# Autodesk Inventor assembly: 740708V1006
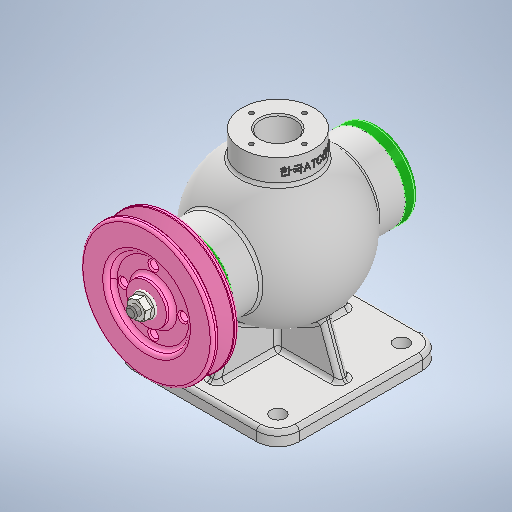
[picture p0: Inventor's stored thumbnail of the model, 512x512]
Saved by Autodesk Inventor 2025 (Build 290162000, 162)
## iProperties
Created: 2024-07
Part Number: 740708V1006
Document SubType Name: Assembly
Designer: parkm
Author: parkm
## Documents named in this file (12)
- C:\Users\parkm\OneDrive\바탕 화면\740708V1006\740708V1006.iam
- C:\Users\parkm\OneDrive\바탕 화면\740708V1006\본체.ipt
- C:\Users\parkm\OneDrive\바탕 화면\740708V1006\뒤커버\뒤커버.ipt
- C:\Users\parkm\OneDrive\바탕 화면\740708V1006\베어링- 6202\베어링- 6202.ipt
- C:\Users\parkm\OneDrive\바탕 화면\740708V1006\편심축\편심축.ipt
- C:\Users\parkm\OneDrive\바탕 화면\740708V1006\칼라\칼라.ipt
- C:\Users\parkm\OneDrive\바탕 화면\740708V1006\앞커버\앞커버.ipt
- C:\Users\parkm\OneDrive\바탕 화면\740708V1006\오일실 15 30 7\오일실 15 30 7.ipt
- C:\Users\parkm\OneDrive\바탕 화면\740708V1006\볼트 M4 x 16\볼트 M4 x 16.ipt
- C:\Users\parkm\OneDrive\바탕 화면\740708V1006\키 4 x 4 x 12\키 4 x 4 x 12.ipt
- C:\Users\parkm\OneDrive\바탕 화면\740708V1006\V-벨트풀리\V-벨트풀리.ipt
- C:\Users\parkm\OneDrive\바탕 화면\740708V1006\너트 M8\너트 M8.ipt
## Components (1 placed, 1 different names)
1. V-벨트풀리:1
